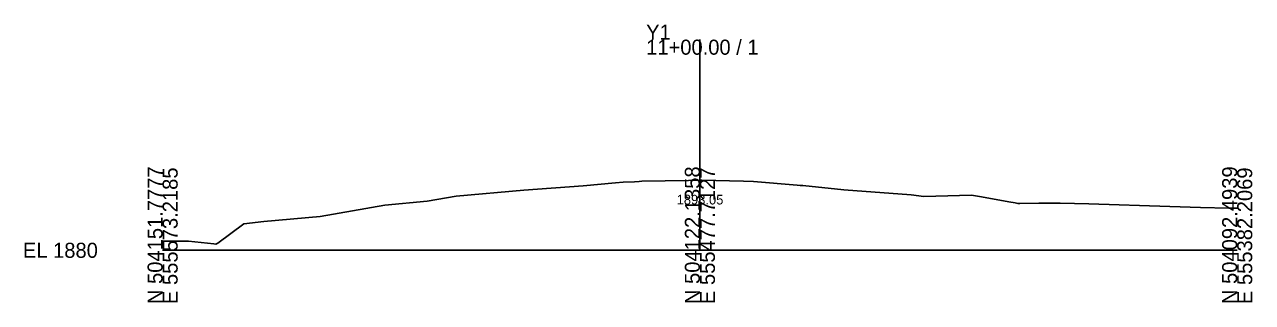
# Model space of a CAD drawing. Extents: x -26 to 1503, y -10 to 5015.
# Drawn here: x -25.7 to 202.8, y 990.3 to 1042 of the extents above; entities that cross this region are included whole.
import ezdxf

# ---------------------------------------------------------------- set-up
doc = ezdxf.new("R2010")
doc.units = 0
for name, color, linetype in [('Default', 7, 'Continuous'), ('Exist Cross Section Cell', 7, 'Continuous'), ('Exist XS Center Line Elevation Label', 7, 'Continuous'), ('Exist XS Ground Line', 7, 'Continuous')]:
    doc.layers.add(name, color=color, linetype=linetype)

msp = doc.modelspace()

# ---------------------------------------------------------------- linework, layer by layer
at = {"layer": 'Exist Cross Section Cell'}
for p, q in [((100, 1000), (100, 1039.17)), ((0, 1000), (100, 1000)), ((100, 1000), (200, 1000))]:
    msp.add_line(p, q, dxfattribs=at)
at = {"layer": 'Exist XS Ground Line'}
for p, q in [((78.3, 1011.97), (84.28, 1012.56)), ((84.28, 1012.56), (85.71, 1012.66)), ((85.71, 1012.66), (87.83, 1012.76)), ((87.83, 1012.76), (88.72, 1012.8)), ((88.72, 1012.8), (89.18, 1012.84)), ((89.18, 1012.84), (97.85, 1012.98)), ((97.85, 1012.98), (100, 1013.05)), ((100, 1013.05), (100.39, 1013.06)), ((100.39, 1013.06), (108.14, 1012.85)), ((108.14, 1012.85), (109.96, 1012.79)), ((109.96, 1012.79), (118.13, 1012.11)), ((54.62, 1010.06), (67.24, 1011.16)), ((67.24, 1011.16), (78.3, 1011.97)), ((118.13, 1012.11), (118.69, 1012.07)), ((118.69, 1012.07), (119.17, 1012.02)), ((119.17, 1012.02), (126.78, 1011.24)), ((126.78, 1011.24), (139.32, 1010.33)), ((139.32, 1010.33), (141.66, 1010.03)), ((143.9, 1010.09), (150.54, 1010.23)), ((150.54, 1010.23), (152.42, 1009.95)), ((29.35, 1006.31), (41.39, 1008.4)), ((41.39, 1008.4), (49.22, 1009.16)), ((49.22, 1009.16), (54.62, 1010.06)), ((141.66, 1010.03), (143.9, 1010.09)), ((152.42, 1009.95), (157.47, 1009.03)), ((157.47, 1009.03), (158.7, 1008.83)), ((158.7, 1008.83), (159.19, 1008.72)), ((159.19, 1008.72), (159.56, 1008.73)), ((159.56, 1008.73), (163.11, 1008.78)), ((163.11, 1008.78), (167.07, 1008.77)), ((167.07, 1008.77), (172.41, 1008.66)), ((172.41, 1008.66), (187.49, 1008.13)), ((187.49, 1008.13), (193.19, 1007.94)), ((193.19, 1007.94), (198.46, 1007.84)), ((198.46, 1007.84), (200, 1007.81)), ((18.82, 1005.34), (29.35, 1006.31)), ((10.28, 1001.34), (15.09, 1004.94)), ((15.09, 1004.94), (18.82, 1005.34)), ((0, 1001.71), (4.84, 1001.7)), ((4.84, 1001.7), (9.55, 1001.22)), ((9.55, 1001.22), (9.89, 1001.17)), ((9.89, 1001.17), (10.28, 1001.34))]:
    msp.add_line(p, q, dxfattribs=at)

# ---------------------------------------------------------------- texts
at = {"layer": 'Default'}
msp.add_text('-', height=0.0001, dxfattribs=at).set_placement((0, 1000))
at = {"layer": 'Exist Cross Section Cell'}
for s, p in [('Y1', (90, 1039.17)), ('11+00.00 / 1', (90, 1036.37)), ('EL 1880', (-26, 998.6))]:
    msp.add_text(s, height=2.8, dxfattribs=at).set_placement(p)
for s, p in [('N 504151.7777', (0, 990)), ('E 555573.2185', (2.8, 990)), ('N 504122.1358', (100, 990)), ('E 555477.7127', (102.8, 990)), ('N 504092.4939', (200, 990)), ('E 555382.2069', (202.8, 990))]:
    msp.add_text(s, height=2.8, rotation=90, dxfattribs=at).set_placement(p)
at = {"layer": 'Exist XS Center Line Elevation Label'}
msp.add_text('1893.05', height=1.8, dxfattribs=at).set_placement((95.67, 1008.52))

doc.saveas('drawing.dxf')
